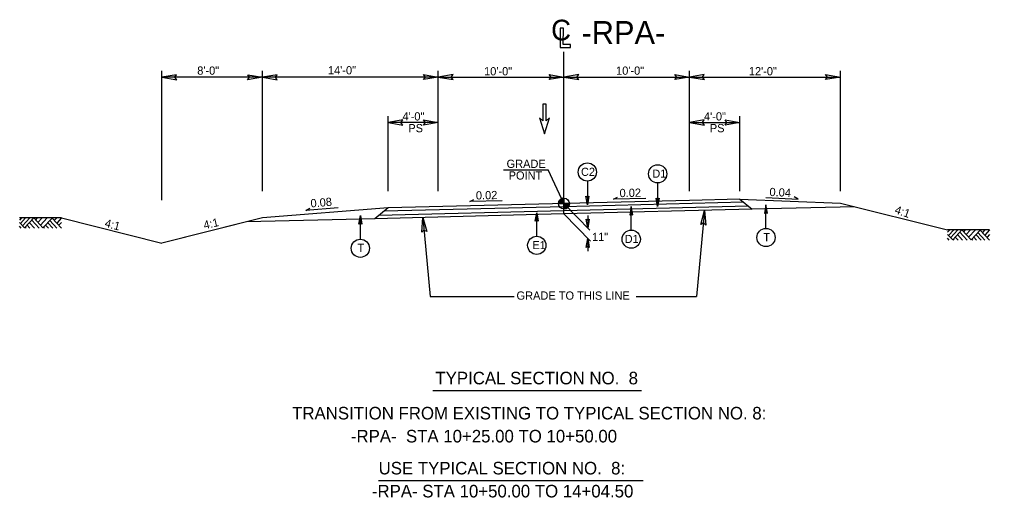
# Model space of a CAD drawing. Extents: x 1901582 to 1902252, y 193723 to 194156.
# Drawn here: x 1902005.9 to 1902083.1, y 193783.4 to 193821.5 of the extents above; entities that cross this region are included whole.
import ezdxf

# ---------------------------------------------------------------- set-up
doc = ezdxf.new("R2010")
doc.units = 0
for name, color, linetype in [('Old_Level_1', 7, 'Continuous'), ('Old_Level_11', 7, 'Continuous'), ('Old_Level_2', 7, 'Continuous'), ('Old_Level_20', 7, 'Continuous'), ('Prop Dimension', 7, 'Continuous'), ('Prop Dimension Text', 7, 'Continuous'), ('Typical Grade Point Symbol CELL', 7, 'Continuous'), ('Typical Pavement Slope Information CELL', 7, 'Continuous'), ('Typical Slope Point Local CELL', 7, 'Continuous'), ('Typical Terminator CELL', 7, 'Continuous'), ('Typical Text Centerline CELL', 7, 'Continuous'), ('Typical Text General CELL', 7, 'Continuous'), ('Typical Text Grade Point CELL', 7, 'Continuous')]:
    doc.layers.add(name, color=color, linetype=linetype)

# ---------------------------------------------------------------- blocks, each defined once
blk = doc.blocks.new('TERMINATOR')
at = {"layer": 'Typical Terminator CELL'}
blk.add_lwpolyline([(-0.469, 0.081), (0, 0), (-0.471, -0.083), (-0.411, 0)], close=True, dxfattribs=at)

msp = doc.modelspace()

# ---------------------------------------------------------------- linework, layer by layer
at = {"layer": 'Old_Level_1'}
for p, q in [((1902017.193, 193807.049), (1902017.193, 193817.347)), ((1902025.193, 193816.847), (1902017.193, 193816.847)), ((1902049.193, 193806.539), (1902034.875, 193806.181)), ((1902059.193, 193807.039), (1902035.192, 193806.439)), ((1902063.487, 193806.897), (1902049.193, 193806.539)), ((1902049.193, 193806.789), (1902051.242, 193804.673)), ((1902063.884, 193806.573), (1902049.193, 193806.206)), ((1902063.193, 193807.139), (1902059.193, 193807.039)), ((1902063.189, 193807.139), (1902064.182, 193806.331)), ((1902063.193, 193807.139), (1902071.193, 193806.819)), ((1902072.333, 193806.534), (1902064.182, 193806.331)), ((1902071.193, 193806.819), (1902079.728, 193804.686)), ((1902035.192, 193806.439), (1902025.193, 193805.639)), ((1902035.192, 193806.439), (1902034.136, 193805.579)), ((1902049.193, 193805.956), (1902034.136, 193805.579)), ((1902049.193, 193806.206), (1902034.453, 193805.837)), ((1902064.182, 193806.331), (1902049.193, 193805.956)), ((1902049.193, 193805.956), (1902051.299, 193803.78)), ((1902051.084, 193805.836), (1902051.084, 193804.836)), ((1902060.384, 193806.236), (1902059.754, 193799.376)), ((1902009.193, 193805.639), (1902009.193, 193805.639)), ((1902025.193, 193805.639), (1902018.872, 193804.059)), ((1902034.136, 193805.579), (1902023.933, 193805.324)), ((1902037.962, 193805.675), (1902038.541, 193799.376)), ((1902051.084, 193804.002), (1902051.084, 193803.002)), ((1902038.541, 193799.376), (1902045.228, 193799.376)), ((1902054.935, 193799.376), (1902059.754, 193799.376))]:
    msp.add_line(p, q, dxfattribs=at)
for points in [[(1902009.193, 193805.639), (1902005.851, 193805.639)], [(1902009.193, 193805.639), (1902017.193, 193803.639)], [(1902025.193, 193805.639), (1902017.193, 193803.639)], [(1902083.07, 193804.686), (1902079.728, 193804.686)]]:
    msp.add_lwpolyline(points, dxfattribs=at)
at = {"layer": 'Old_Level_11'}
for p, q in [((1902049.193, 193805.956), (1902049.193, 193818.862)), ((1902051.057, 193808.571), (1902051.057, 193806.697)), ((1902056.651, 193808.426), (1902056.651, 193806.552)), ((1902054.548, 193804.675), (1902054.548, 193806.549)), ((1902065.273, 193804.807), (1902065.273, 193806.682)), ((1902032.989, 193803.953), (1902032.989, 193805.827)), ((1902047.029, 193804.187), (1902047.029, 193806.061)), ((1902006.021, 193805.639), (1902005.851, 193805.456)), ((1902006.255, 193804.842), (1902005.851, 193805.277)), ((1902005.985, 193804.834), (1902005.851, 193804.977)), ((1902006.341, 193805.639), (1902005.927, 193805.195)), ((1902006.674, 193805.639), (1902006.094, 193805.016)), ((1902006.996, 193805.638), (1902006.255, 193804.842)), ((1902006.681, 193804.834), (1902006.464, 193805.067)), ((1902007.047, 193804.834), (1902006.647, 193805.263)), ((1902007.417, 193804.834), (1902006.831, 193805.462)), ((1902007.727, 193804.852), (1902006.996, 193805.638)), ((1902007.26, 193805.639), (1902007.127, 193805.496)), ((1902007.662, 193805.639), (1902007.329, 193805.28)), ((1902008.06, 193805.639), (1902007.527, 193805.066)), ((1902008.451, 193805.631), (1902007.727, 193804.852)), ((1902008.163, 193804.834), (1902007.936, 193805.077)), ((1902008.51, 193804.834), (1902008.109, 193805.263)), ((1902008.819, 193804.834), (1902008.265, 193805.43)), ((1902009.193, 193804.834), (1902008.451, 193805.631)), ((1902008.818, 193805.639), (1902008.631, 193805.438)), ((1902009.193, 193805.639), (1902008.818, 193805.236)), ((1902009.193, 193805.277), (1902008.987, 193805.055)), ((1902006.386, 193804.834), (1902006.317, 193804.908)), ((1902007.852, 193804.834), (1902007.781, 193804.91)), ((1902079.898, 193804.686), (1902079.728, 193804.503)), ((1902080.132, 193803.889), (1902079.728, 193804.324)), ((1902080.218, 193804.686), (1902079.804, 193804.242)), ((1902080.551, 193804.686), (1902079.971, 193804.063)), ((1902080.873, 193804.685), (1902080.132, 193803.889)), ((1902080.924, 193803.881), (1902080.524, 193804.31)), ((1902081.294, 193803.881), (1902080.708, 193804.509)), ((1902081.604, 193803.899), (1902080.873, 193804.685)), ((1902081.137, 193804.686), (1902081.004, 193804.543)), ((1902081.539, 193804.686), (1902081.206, 193804.327)), ((1902081.937, 193804.686), (1902081.404, 193804.113)), ((1902082.328, 193804.678), (1902081.604, 193803.899)), ((1902082.387, 193803.881), (1902081.986, 193804.31)), ((1902082.696, 193803.881), (1902082.142, 193804.477)), ((1902083.07, 193803.881), (1902082.328, 193804.678)), ((1902082.695, 193804.686), (1902082.508, 193804.485)), ((1902083.07, 193804.686), (1902082.695, 193804.283)), ((1902083.07, 193804.324), (1902082.864, 193804.102)), ((1902079.862, 193803.881), (1902079.728, 193804.024)), ((1902080.263, 193803.881), (1902080.194, 193803.955)), ((1902080.558, 193803.881), (1902080.341, 193804.114)), ((1902081.729, 193803.881), (1902081.658, 193803.957)), ((1902082.04, 193803.881), (1902081.813, 193804.124)), ((1902038.751, 193791.898), (1902055.377, 193791.898)), ((1902034.443, 193784.725), (1902054.186, 193784.725)), ((1902034.443, 193784.725), (1902055.497, 193784.725))]:
    msp.add_line(p, q, dxfattribs=at)
for points in [[(1902051.173, 193807.369), (1902051.057, 193806.697), (1902050.938, 193807.372), (1902051.057, 193807.287)], [(1902054.664, 193805.878), (1902054.548, 193806.549), (1902054.429, 193805.874), (1902054.548, 193805.96)], [(1902056.767, 193807.224), (1902056.651, 193806.552), (1902056.532, 193807.227), (1902056.651, 193807.141)], [(1902065.389, 193806.01), (1902065.273, 193806.682), (1902065.154, 193806.006), (1902065.273, 193806.092)], [(1902032.874, 193805.155), (1902032.989, 193805.827), (1902033.109, 193805.152), (1902032.989, 193805.237)], [(1902046.914, 193805.389), (1902047.029, 193806.061), (1902047.149, 193805.386), (1902047.029, 193805.471)]]:
    msp.add_lwpolyline(points, close=True, dxfattribs=at)
for centre in [(1902051.057, 193809.297), (1902056.651, 193809.151), (1902054.548, 193803.95), (1902065.273, 193804.082), (1902032.989, 193803.227), (1902047.029, 193803.462)]:
    msp.add_circle(centre, 0.725, dxfattribs=at)
at = {"layer": 'Prop Dimension'}
for p, q in [((1902025.193, 193807.774), (1902025.193, 193817.347)), ((1902039.193, 193807.774), (1902039.193, 193817.362)), ((1902059.193, 193807.775), (1902059.193, 193817.362)), ((1902071.193, 193807.775), (1902071.193, 193817.362)), ((1902039.193, 193816.862), (1902025.193, 193816.847)), ((1902039.193, 193816.862), (1902049.193, 193816.862)), ((1902049.193, 193816.862), (1902059.193, 193816.862)), ((1902059.193, 193816.862), (1902071.193, 193816.862)), ((1902035.193, 193807.774), (1902035.193, 193813.749)), ((1902063.193, 193807.775), (1902063.193, 193813.749)), ((1902039.193, 193813.249), (1902035.193, 193813.249)), ((1902059.193, 193813.249), (1902063.193, 193813.249))]:
    msp.add_line(p, q, dxfattribs=at)
msp.add_lwpolyline([(1902048.036, 193813.614), (1902047.766, 193813.364), (1902047.766, 193814.698), (1902047.516, 193814.698), (1902047.516, 193813.364), (1902047.245, 193813.614), (1902047.641, 193812.343)], close=True, dxfattribs=at)
msp.add_lwpolyline([(1902048.036, 193813.614), (1902047.766, 193813.364), (1902047.766, 193814.698), (1902047.516, 193814.698), (1902047.516, 193813.364), (1902047.245, 193813.614), (1902047.641, 193812.343)], close=True, dxfattribs=at)
at = {"layer": 'Typical Grade Point Symbol CELL'}
for p, q in [((1902048.763, 193806.789), (1902049.193, 193806.789)), ((1902049.193, 193806.789), (1902049.193, 193807.219)), ((1902049.194, 193806.36), (1902049.193, 193806.789)), ((1902049.623, 193806.789), (1902049.193, 193806.789)), ((1902049.193, 193806.789), (1902049.194, 193806.36))]:
    msp.add_line(p, q, dxfattribs=at)
for points in [[(1902048.768, 193806.851), (1902048.768, 193806.789)], [(1902048.777, 193806.894), (1902048.777, 193806.789)], [(1902048.785, 193806.924), (1902048.785, 193806.789)], [(1902048.794, 193806.948), (1902048.794, 193806.789)], [(1902048.803, 193806.968), (1902048.803, 193806.789)], [(1902048.811, 193806.986), (1902048.811, 193806.789)], [(1902048.82, 193807.001), (1902048.82, 193806.789)], [(1902048.828, 193807.016), (1902048.828, 193806.789)], [(1902048.837, 193807.029), (1902048.837, 193806.789)], [(1902048.846, 193807.042), (1902048.846, 193806.789)], [(1902048.854, 193807.053), (1902048.854, 193806.789)], [(1902048.863, 193807.063), (1902048.863, 193806.789)], [(1902048.871, 193807.074), (1902048.871, 193806.789)], [(1902048.88, 193807.084), (1902048.88, 193806.789)], [(1902048.889, 193807.092), (1902048.889, 193806.789)], [(1902048.897, 193807.101), (1902048.897, 193806.789)], [(1902048.906, 193807.108), (1902048.906, 193806.789)], [(1902048.914, 193807.116), (1902048.914, 193806.789)], [(1902048.923, 193807.124), (1902048.923, 193806.789)], [(1902048.931, 193807.13), (1902048.931, 193806.789)], [(1902048.94, 193807.136), (1902048.94, 193806.789)], [(1902048.949, 193807.143), (1902048.949, 193806.789)], [(1902048.957, 193807.148), (1902048.957, 193806.789)], [(1902048.966, 193807.154), (1902048.966, 193806.789)], [(1902048.974, 193807.159), (1902048.974, 193806.789)], [(1902048.983, 193807.164), (1902048.983, 193806.789)], [(1902048.992, 193807.168), (1902048.992, 193806.789)], [(1902049, 193807.173), (1902049, 193806.789)], [(1902049.009, 193807.177), (1902049.009, 193806.789)], [(1902049.017, 193807.181), (1902049.017, 193806.789)], [(1902049.026, 193807.185), (1902049.026, 193806.789)], [(1902049.035, 193807.189), (1902049.035, 193806.789)], [(1902049.043, 193807.192), (1902049.043, 193806.789)], [(1902049.052, 193807.195), (1902049.052, 193806.789)], [(1902049.06, 193807.198), (1902049.06, 193806.789)], [(1902049.069, 193807.201), (1902049.069, 193806.789)], [(1902049.078, 193807.203), (1902049.078, 193806.789)], [(1902049.086, 193807.206), (1902049.086, 193806.789)], [(1902049.095, 193807.208), (1902049.095, 193806.789)], [(1902049.103, 193807.21), (1902049.103, 193806.789)], [(1902049.112, 193807.211), (1902049.112, 193806.789)], [(1902049.121, 193807.213), (1902049.121, 193806.789)], [(1902049.129, 193807.214), (1902049.129, 193806.789)], [(1902049.138, 193807.215), (1902049.138, 193806.789)], [(1902049.146, 193807.216), (1902049.146, 193806.789)], [(1902049.155, 193807.217), (1902049.155, 193806.789)], [(1902049.164, 193807.218), (1902049.164, 193806.789)], [(1902049.172, 193807.218), (1902049.172, 193806.789)], [(1902049.181, 193807.219), (1902049.181, 193806.789)], [(1902049.189, 193807.219), (1902049.189, 193807.219), (1902049.189, 193806.789)], [(1902049.2, 193806.789), (1902049.2, 193806.36), (1902049.2, 193806.36)], [(1902049.208, 193806.789), (1902049.208, 193806.36)], [(1902049.217, 193806.789), (1902049.217, 193806.361)], [(1902049.226, 193806.789), (1902049.226, 193806.361)], [(1902049.234, 193806.789), (1902049.234, 193806.362)], [(1902049.243, 193806.789), (1902049.243, 193806.363)], [(1902049.251, 193806.789), (1902049.251, 193806.364)], [(1902049.26, 193806.789), (1902049.26, 193806.365)], [(1902049.269, 193806.789), (1902049.269, 193806.366)], [(1902049.277, 193806.789), (1902049.277, 193806.368)], [(1902049.286, 193806.789), (1902049.286, 193806.37)], [(1902049.294, 193806.789), (1902049.294, 193806.372)], [(1902049.303, 193806.789), (1902049.303, 193806.374)], [(1902049.312, 193806.789), (1902049.312, 193806.377)], [(1902049.32, 193806.789), (1902049.32, 193806.379)], [(1902049.329, 193806.789), (1902049.329, 193806.382)], [(1902049.337, 193806.789), (1902049.337, 193806.385)], [(1902049.346, 193806.789), (1902049.346, 193806.387)], [(1902049.355, 193806.789), (1902049.355, 193806.391)], [(1902049.363, 193806.789), (1902049.363, 193806.395)], [(1902049.372, 193806.789), (1902049.372, 193806.399)], [(1902049.38, 193806.789), (1902049.38, 193806.403)], [(1902049.389, 193806.789), (1902049.389, 193806.407)], [(1902049.397, 193806.789), (1902049.397, 193806.411)], [(1902049.406, 193806.789), (1902049.406, 193806.416)], [(1902049.415, 193806.789), (1902049.415, 193806.421)], [(1902049.423, 193806.789), (1902049.423, 193806.427)], [(1902049.432, 193806.789), (1902049.432, 193806.432)], [(1902049.44, 193806.789), (1902049.44, 193806.438)], [(1902049.449, 193806.789), (1902049.449, 193806.444)], [(1902049.458, 193806.789), (1902049.458, 193806.45)], [(1902049.466, 193806.789), (1902049.466, 193806.457)], [(1902049.475, 193806.789), (1902049.475, 193806.465)], [(1902049.483, 193806.789), (1902049.483, 193806.472)], [(1902049.492, 193806.789), (1902049.492, 193806.48)], [(1902049.501, 193806.789), (1902049.501, 193806.489)], [(1902049.509, 193806.789), (1902049.509, 193806.498)], [(1902049.518, 193806.789), (1902049.518, 193806.508)], [(1902049.526, 193806.789), (1902049.526, 193806.518)], [(1902049.535, 193806.789), (1902049.535, 193806.529)], [(1902049.544, 193806.789), (1902049.544, 193806.54)], [(1902049.552, 193806.789), (1902049.552, 193806.553)], [(1902049.561, 193806.789), (1902049.561, 193806.566)], [(1902049.569, 193806.789), (1902049.569, 193806.581)], [(1902049.578, 193806.789), (1902049.578, 193806.597)], [(1902049.587, 193806.789), (1902049.587, 193806.616)], [(1902049.595, 193806.789), (1902049.595, 193806.636)], [(1902049.604, 193806.789), (1902049.604, 193806.661)], [(1902049.612, 193806.789), (1902049.612, 193806.692)], [(1902049.621, 193806.789), (1902049.621, 193806.743)]]:
    msp.add_lwpolyline(points, dxfattribs=at)
msp.add_circle((1902049.194, 193806.79), 0.43, dxfattribs=at)
for start, end in [(90.00952, 180.00952), (270.00952, 0.00952)]:
    msp.add_arc((1902049.194, 193806.79), 0.43, start, end, dxfattribs=at)
at = {"layer": 'Typical Pavement Slope Information CELL'}
for p, q in [((1902053.131, 193807.136), (1902053.463, 193807.304)), ((1902067.845, 193807.136), (1902067.517, 193807.312)), ((1902041.696, 193806.946), (1902042.028, 193807.115)), ((1902044.283, 193807.01), (1902041.696, 193806.946)), ((1902055.718, 193807.199), (1902053.131, 193807.136)), ((1902065.26, 193807.265), (1902067.845, 193807.136)), ((1902031.234, 193806.443), (1902028.654, 193806.238)), ((1902028.654, 193806.238), (1902028.977, 193806.424))]:
    msp.add_line(p, q, dxfattribs=at)
at = {"layer": 'Typical Terminator CELL'}
for points in [[(1902018.365, 193817.049), (1902017.193, 193816.847), (1902018.371, 193816.639), (1902018.221, 193816.847)], [(1902024.021, 193817.049), (1902025.193, 193816.847), (1902024.015, 193816.639), (1902024.164, 193816.847)], [(1902026.365, 193817.049), (1902025.193, 193816.847), (1902026.371, 193816.639), (1902026.221, 193816.847)], [(1902038.021, 193817.064), (1902039.193, 193816.862), (1902038.015, 193816.654), (1902038.164, 193816.862)], [(1902040.365, 193817.064), (1902039.193, 193816.862), (1902040.371, 193816.654), (1902040.221, 193816.862)], [(1902048.021, 193817.064), (1902049.193, 193816.862), (1902048.015, 193816.654), (1902048.164, 193816.862)], [(1902050.365, 193817.064), (1902049.193, 193816.862), (1902050.371, 193816.654), (1902050.221, 193816.862)], [(1902058.021, 193817.064), (1902059.193, 193816.862), (1902058.015, 193816.654), (1902058.164, 193816.862)], [(1902060.365, 193817.064), (1902059.193, 193816.862), (1902060.371, 193816.654), (1902060.221, 193816.862)], [(1902070.021, 193817.064), (1902071.193, 193816.862), (1902070.015, 193816.654), (1902070.164, 193816.862)], [(1902036.365, 193813.45), (1902035.193, 193813.249), (1902036.371, 193813.04), (1902036.221, 193813.249)], [(1902038.021, 193813.45), (1902039.193, 193813.249), (1902038.015, 193813.04), (1902038.164, 193813.249)], [(1902060.365, 193813.45), (1902059.193, 193813.249), (1902060.371, 193813.04), (1902060.221, 193813.249)], [(1902062.021, 193813.45), (1902063.193, 193813.249), (1902062.015, 193813.04), (1902062.164, 193813.249)], [(1902060.084, 193805.119), (1902060.384, 193806.236), (1902060.481, 193805.076), (1902060.292, 193805.239)], [(1902037.871, 193804.522), (1902037.962, 193805.675), (1902038.269, 193804.552), (1902038.053, 193804.679)]]:
    msp.add_lwpolyline(points, close=True, dxfattribs=at)
at = {"layer": 'Typical Text Centerline CELL'}
msp.add_lwpolyline([(1902048.894, 193819.45), (1902048.894, 193819.226), (1902049.703, 193819.225), (1902049.703, 193819.449), (1902049.143, 193819.449), (1902049.144, 193820.762), (1902048.895, 193820.763)], close=True, dxfattribs=at)
at = {"layer": 'Typical Text Grade Point CELL'}
for p in [(1902044.393, 193809.459), (1902049.193, 193806.789)]:
    msp.add_line(p, (1902047.931, 193809.459), dxfattribs=at)

# ---------------------------------------------------------------- block references
at = {"layer": 'Old_Level_1', "xscale": 1.5, "yscale": 1.5}
for p, rotation in [((1902051.084, 193804.836), -90), ((1902051.084, 193804.002), 90)]:
    msp.add_blockref('TERMINATOR', p, dxfattribs=dict(at, rotation=rotation))

# ---------------------------------------------------------------- texts
at = {"layer": 'Old_Level_1'}
for s, p in [('8\'-0"', (1902020.004, 193817.045)), ('4\'-0"', (1902036.338, 193813.401)), ('4\'-0"', (1902060.338, 193813.401))]:
    msp.add_text(s, height=0.656, dxfattribs=at).set_placement(p)
msp.add_text('4:1', height=0.656, rotation=345.24563, dxfattribs=at).set_placement((1902012.593, 193804.943))
at = {"layer": 'Old_Level_11'}
for s, p in [('TYPICAL SECTION NO.  8', (1902038.962, 193792.392)), ('TRANSITION FROM EXISTING TO TYPICAL SECTION NO. 8: ', (1902027.558, 193789.597)), ('-RPA-  STA 10+25.00 TO 10+50.00', (1902032.234, 193787.766)), ('USE TYPICAL SECTION NO.  8:', (1902034.443, 193785.219)), ('-RPA- STA 10+50.00 TO 14+04.50', (1902033.904, 193783.388))]:
    msp.add_text(s, height=1, dxfattribs=at).set_placement(p)
at = {"layer": 'Old_Level_2'}
for s, rotation, p in [('0.04', 357.35093, (1902065.539, 193807.393)), ('0.02', 1.19158, (1902042.189, 193807.107)), ('0.02', 1.19158, (1902053.624, 193807.296))]:
    msp.add_text(s, height=0.656, rotation=rotation, dxfattribs=at).set_placement(p)
at = {"layer": 'Old_Level_20'}
for s, height, p in [('C2', 0.6491, (1902050.551, 193808.99)), ('D1', 0.6491, (1902056.229, 193808.845)), ('11"', 0.6491, (1902051.43, 193803.808)), ('D1', 0.6491, (1902054.026, 193803.646)), ('T', 0.649, (1902065.062, 193803.789)), ('T', 0.649, (1902032.762, 193802.934)), ('E1', 0.6491, (1902046.684, 193803.158))]:
    msp.add_text(s, height=height, dxfattribs=at).set_placement(p)
at = {"layer": 'Prop Dimension Text'}
for s, p in [('14\'-0"', (1902030.409, 193817.073)), ('10\'-0"', (1902042.835, 193816.994)), ('10\'-0"', (1902053.34, 193817.044)), ('12\'-0"', (1902063.906, 193816.997)), ('PS', (1902036.804, 193812.463)), ('PS', (1902060.804, 193812.463))]:
    msp.add_text(s, height=0.656, dxfattribs=at).set_placement(p)
at = {"layer": 'Typical Pavement Slope Information CELL'}
msp.add_text('0.08', height=0.656, rotation=4.80528, dxfattribs=at).set_placement((1902029.048, 193806.473))
at = {"layer": 'Typical Slope Point Local CELL'}
for rotation, p in [(341.09863, (1902075.459, 193806.028)), (13.0197, (1902020.582, 193804.732))]:
    msp.add_text('4:1', height=0.656, rotation=rotation, dxfattribs=at).set_placement(p)
at = {"layer": 'Typical Text Centerline CELL'}
msp.add_text('C', height=1.64, dxfattribs=at).set_placement((1902048.172, 193819.786))
msp.add_text('-RPA-', height=1.8323, rotation=0.00002, dxfattribs=at).set_placement((1902050.589, 193819.485))
at = {"layer": 'Typical Text General CELL'}
msp.add_text('GRADE TO THIS LINE', height=0.656, dxfattribs=at).set_placement((1902045.417, 193799.133))
at = {"layer": 'Typical Text Grade Point CELL'}
for s, p in [('GRADE', (1902044.625, 193809.625)), ('POINT', (1902044.788, 193808.697))]:
    msp.add_text(s, height=0.656, rotation=360, dxfattribs=at).set_placement(p)

doc.saveas('drawing.dxf')
